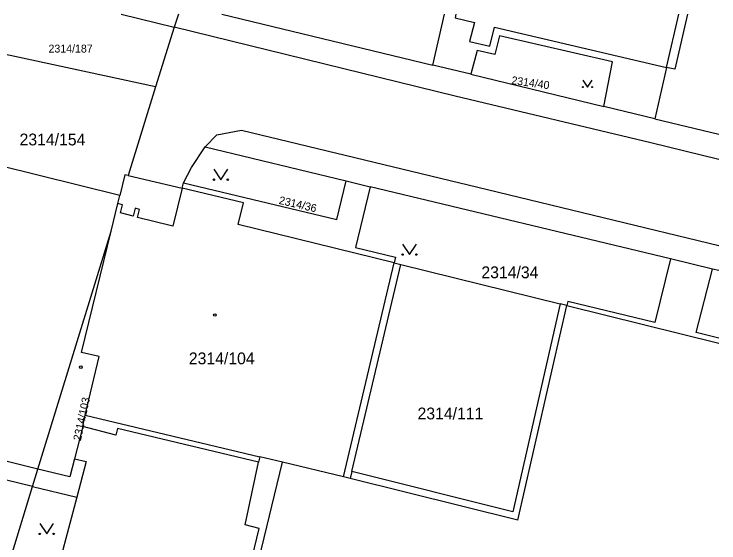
# Model space of a CAD drawing. Extents: x -599970 to -599524, y -1154772 to -1154457.
# Drawn here: x -599579.5 to -599528.8, y -1154593 to -1154554.9 of the extents above; entities that cross this region are included whole.
import ezdxf

# ---------------------------------------------------------------- set-up
doc = ezdxf.new("R2010")
doc.units = 0
doc.layers.add('Z-KATASTRALNI MAPA', color=7, linetype='Continuous')

msp = doc.modelspace()

# ---------------------------------------------------------------- linework, layer by layer
at = {"layer": 'Z-KATASTRALNI MAPA'}
for p, q in [((-599567.7, -1154554.95), (-599567.99, -1154555.9)), ((-599564.56, -1154554.95), (-599549.37, -1154558.62)), ((-599549.37, -1154558.62), (-599548.54, -1154554.95)), ((-599547.71, -1154554.95), (-599547.77, -1154555.23)), ((-599547.77, -1154555.23), (-599546.38, -1154555.56)), ((-599532.54, -1154558.8), (-599531.65, -1154554.95)), ((-599546.38, -1154555.56), (-599546.74, -1154556.93)), ((-599567.99, -1154555.9), (-599569.35, -1154560.2)), ((-599545.27, -1154557.25), (-599544.92, -1154555.9)), ((-599544.92, -1154555.9), (-599532.54, -1154558.8)), ((-599569.35, -1154560.2), (-599583.47, -1154557.16)), ((-599546.74, -1154556.93), (-599545.27, -1154557.25)), ((-599546.63, -1154559.28), (-599549.37, -1154558.62)), ((-599546.63, -1154559.28), (-599537.06, -1154561.61)), ((-599569.35, -1154560.2), (-599571.31, -1154566.58)), ((-599533.39, -1154562.49), (-599537.06, -1154561.61)), ((-599571.91, -1154568.01), (-599585.22, -1154564.72)), ((-599565.76, -1154564.52), (-599555.62, -1154566.96)), ((-599555.62, -1154566.96), (-599553.88, -1154567.39)), ((-599567.43, -1154567.5), (-599568.1, -1154570.23)), ((-599563.01, -1154568.55), (-599567.43, -1154567.5)), ((-599532.25, -1154572.59), (-599553.88, -1154567.39)), ((-599563.39, -1154570.11), (-599563.01, -1154568.55)), ((-599571.73, -1154568.69), (-599572.06, -1154568.6)), ((-599571.87, -1154569.27), (-599571.73, -1154568.69)), ((-599570.81, -1154568.94), (-599570.95, -1154569.5)), ((-599570.51, -1154569.02), (-599570.81, -1154568.94)), ((-599570.65, -1154569.6), (-599570.51, -1154569.02)), ((-599570.95, -1154569.5), (-599571.87, -1154569.27)), ((-599568.1, -1154570.23), (-599570.65, -1154569.6)), ((-599552.16, -1154572.86), (-599563.39, -1154570.11)), ((-599529.22, -1154573.32), (-599532.25, -1154572.59)), ((-599555.81, -1154588.28), (-599552.16, -1154572.86)), ((-599555.2, -1154587.91), (-599551.67, -1154572.98)), ((-599551.67, -1154572.98), (-599540.2, -1154575.83)), ((-599543.24, -1154591.41), (-599539.72, -1154575.95)), ((-599539.72, -1154575.95), (-599528.77, -1154578.65)), ((-599577.82, -1154587.73), (-599594.85, -1154583.55)), ((-599574.4, -1154583.84), (-599561.84, -1154586.84)), ((-599575.18, -1154587), (-599575.51, -1154588.3)), ((-599562.95, -1154598.56), (-599560.21, -1154587.23)), ((-599575.51, -1154588.3), (-599577.82, -1154587.73)), ((-599543.24, -1154591.41), (-599555.32, -1154588.4)), ((-599581.98, -1154601.27), (-599578.2, -1154588.98)), ((-599578.2, -1154588.98), (-599575.02, -1154589.76)), ((-599575.02, -1154589.76), (-599578.41, -1154602.57))]:
    msp.add_line(p, q, dxfattribs=at)
for points in [[(-599571.82, -1154554.95), (-599567.99, -1154555.9)], [(-599531.03, -1154554.95), (-599531.95, -1154558.93), (-599532.54, -1154558.8), (-599533.39, -1154562.49)], [(-599528.77, -1154565.42), (-599533.67, -1154564.23), (-599547.76, -1154560.86), (-599567.99, -1154555.9)], [(-599537.06, -1154561.61), (-599536.43, -1154558.4), (-599544.57, -1154556.51), (-599544.91, -1154557.86), (-599546.17, -1154557.57), (-599546.63, -1154559.28)], [(-599538.565, -1154559.707), (-599538.23, -1154560.21), (-599537.895, -1154559.707)], [(-599533.39, -1154562.49), (-599528.77, -1154563.6)], [(-599578.2, -1154588.98), (-599595.57, -1154584.75), (-599590.49, -1154563.45)], [(-599565.76, -1154564.52), (-599564.93, -1154563.65), (-599563.16, -1154563.32), (-599545.44, -1154567.59), (-599528.77, -1154571.63)], [(-599567.34, -1154567.11), (-599566.75, -1154566.01), (-599565.76, -1154564.52)], [(-599571.31, -1154566.58), (-599571.55, -1154566.52), (-599571.91, -1154568.01)], [(-599565.14, -1154566.13), (-599564.64, -1154566.88), (-599564.14, -1154566.13)], [(-599571.31, -1154566.58), (-599567.43, -1154567.5), (-599567.34, -1154567.11)], [(-599567.34, -1154567.11), (-599556.28, -1154569.76), (-599555.62, -1154566.96)], [(-599553.88, -1154567.39), (-599554.93, -1154571.77), (-599552.06, -1154572.47), (-599552.16, -1154572.86), (-599551.67, -1154572.98)], [(-599572.54, -1154570.58), (-599572.06, -1154568.6), (-599571.91, -1154568.01)], [(-599578.2, -1154588.98), (-599577.82, -1154587.73), (-599572.54, -1154570.58)], [(-599574.58, -1154584.66), (-599574.4, -1154583.84), (-599573.41, -1154579.63), (-599574.67, -1154579.32), (-599572.54, -1154570.58)], [(-599551.55, -1154571.529), (-599551.05, -1154572.28), (-599550.55, -1154571.529)], [(-599532.25, -1154572.59), (-599533.38, -1154577.18), (-599539.65, -1154575.66), (-599539.72, -1154575.95), (-599540.2, -1154575.83)], [(-599528.77, -1154578.31), (-599530.4, -1154577.9), (-599529.22, -1154573.32)], [(-599528.77, -1154573.42), (-599529.22, -1154573.32)], [(-599540.2, -1154575.83), (-599543.61, -1154590.81), (-599555.2, -1154587.91)], [(-599574.58, -1154584.66), (-599575.18, -1154587), (-599574.34, -1154587.19), (-599575.02, -1154589.76)], [(-599561.93, -1154587.23), (-599572.09, -1154584.8), (-599572.2, -1154585.28), (-599574.58, -1154584.66)], [(-599555.2, -1154587.91), (-599555.32, -1154588.4), (-599555.81, -1154588.28), (-599560.21, -1154587.23), (-599561.84, -1154586.84), (-599561.93, -1154587.23)], [(-599567.16, -1154608.2), (-599563.73, -1154594.52), (-599562.55, -1154594.79), (-599561.88, -1154592.02), (-599562.89, -1154591.75), (-599561.93, -1154587.23)], [(-599577.68, -1154591.65), (-599577.18, -1154592.4), (-599576.68, -1154591.65)]]:
    msp.add_lwpolyline(points, dxfattribs=at)
for centre, radius in [((-599538.565, -1154560.21), 0.0335), ((-599537.895, -1154560.21), 0.0335), ((-599565.14, -1154566.88), 0.05), ((-599564.14, -1154566.88), 0.05), ((-599551.55, -1154572.28), 0.05), ((-599550.55, -1154572.28), 0.05), ((-599565.073, -1154576.63), 0.0875), ((-599574.723, -1154580.39), 0.0875), ((-599577.68, -1154592.4), 0.05), ((-599576.68, -1154592.4), 0.05)]:
    msp.add_circle(centre, radius, dxfattribs=at)

# ---------------------------------------------------------------- texts
for s, height, p in [('2314/187', 0.57, (-599577.05, -1154557.72)), ('2314/154', 0.85, (-599579.136, -1154564.41)), ('2314/34', 0.85, (-599545.876, -1154573.98)), ('2314/104', 0.85, (-599566.946, -1154580.18)), ('2314/111', 0.85, (-599550.475, -1154584.15))]:
    msp.add_text(s, height=height, dxfattribs=at).set_placement(p)
for s, rotation, p in [('2314/40', 352, (-599543.744, -1154559.983)), ('2314/36', 347, (-599560.499, -1154568.615)), ('2314/103', 78, (-599574.724, -1154585.736))]:
    msp.add_text(s, height=0.57, rotation=rotation, dxfattribs=at).set_placement(p)

doc.saveas('drawing.dxf')
